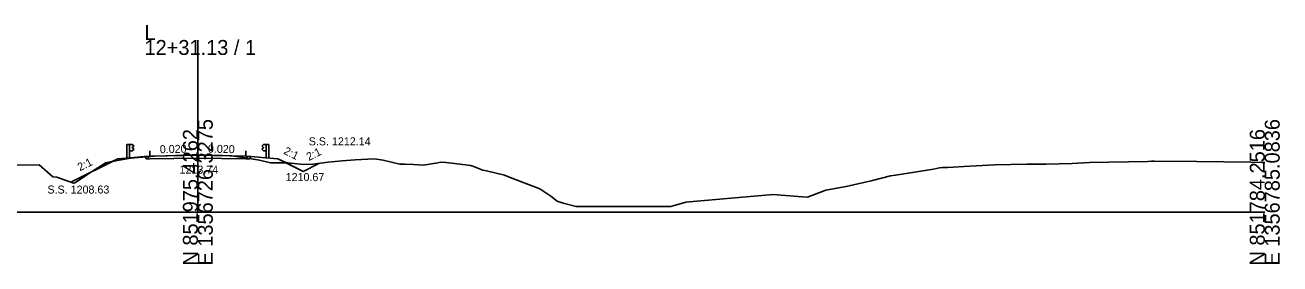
# Model space of a CAD drawing. Extents: x -26 to 3203, y -10 to 4066.
# Drawn here: x 2967.6 to 3202.8, y -9.7 to 35.1 of the extents above; entities that cross this region are included whole.
import ezdxf

# ---------------------------------------------------------------- set-up
doc = ezdxf.new("R2010")
doc.units = 0
for name, color, linetype in [('Exist Cross Section Cell', 7, 'Continuous'), ('Exist XS Center Line Elevation Label', 7, 'Continuous'), ('Exist XS Ground Line', 7, 'Continuous'), ('Prop XS Ditch Standard Text', 7, 'Continuous'), ('Prop XS Dump Level', 7, 'Continuous'), ('Prop XS Earthwork Shape', 7, 'Continuous'), ('Prop XS EOT Tick Mark', 7, 'Continuous'), ('Prop XS Finish Grade', 7, 'Continuous'), ('Prop XS Finish Grade Earthwork', 7, 'Continuous'), ('Prop XS Finish Grade Pavement', 7, 'Continuous'), ('Prop XS Guardrail', 7, 'Continuous'), ('Prop XS Pvmt Edge Slope', 7, 'Continuous'), ('Prop XS SE Text', 7, 'Continuous'), ('Prop XS Side Slope Text', 7, 'Continuous'), ('Prop XS SS Elevation Text', 7, 'Continuous'), ('Prop XS Subgrade Earthwork', 7, 'Continuous')]:
    doc.layers.add(name, color=color, linetype=linetype)

msp = doc.modelspace()

# ---------------------------------------------------------------- linework, layer by layer
at = {"layer": 'Exist Cross Section Cell'}
for p, q in [((3000, 0), (3000, 32.31)), ((2800, 0), (3000, 0)), ((3000, 0), (3200, 0))]:
    msp.add_line(p, q, dxfattribs=at)
at = {"layer": 'Exist XS Ground Line'}
msp.add_lwpolyline([(2965.91, 8.82), (2970.24, 8.91), (2972.79, 6.67), (2973.56, 6.61), (2976.67, 5.44), (2976.92, 5.5), (2977.26, 5.7), (2979.55, 7.26), (2982.41, 9.1), (2982.72, 9.26), (2984.89, 9.68), (2986.66, 10.02), (2987.36, 10.16), (2991.86, 10.54), (2994.24, 10.56), (2998.94, 10.77), (3000, 10.74), (3004.65, 10.63), (3006.35, 10.61), (3008.5, 10.27), (3011.55, 9.76), (3013.62, 9.29), (3016.86, 9.24), (3019.83, 8.98), (3021.58, 8.99), (3024.46, 9.38), (3027.05, 9.67), (3029.5, 9.82), (3033.05, 10), (3034.77, 9.77), (3037.85, 9.05), (3038.78, 9.02), (3040.42, 8.94), (3042.33, 8.84), (3043.83, 9.09), (3044.99, 9.28), (3045.51, 9.37), (3046.47, 9.35), (3048.17, 9.12), (3048.56, 9.08), (3050.16, 8.91), (3051.13, 8.76), (3051.55, 8.67), (3052.5, 8.25), (3053.43, 7.88), (3054.11, 7.78), (3057.51, 6.95), (3058.54, 6.49), (3064.09, 4.4), (3066.18, 3.02), (3067.37, 2.05), (3068.46, 1.71), (3070.89, 1.07), (3075.46, 1.07), (3086.99, 1.07), (3088.17, 1.07), (3088.69, 1.07), (3089.08, 1.18), (3091.48, 1.89), (3092.86, 2.02), (3102.12, 2.8), (3107.13, 3.29), (3107.81, 3.33), (3113.36, 2.92), (3114.29, 2.85), (3117.74, 4.15), (3121.54, 4.84), (3126.24, 5.91), (3129.86, 6.82), (3130.76, 6.93), (3137.9, 8.08), (3139.05, 8.31), (3139.61, 8.38), (3140.55, 8.4), (3144.7, 8.65), (3149.42, 8.91), (3155.37, 9.03), (3159.04, 9.04), (3163.88, 9.17), (3167.17, 9.32), (3178.08, 9.55), (3178.78, 9.57), (3179.29, 9.58), (3187.27, 9.52), (3197.39, 9.37), (3199.47, 9.34), (3200, 9.33)], dxfattribs=at)
at = {"layer": 'Prop XS Dump Level'}
for p, q in [((2991, 10.53), (3000, 10.71)), ((3000, 10.71), (3009, 10.53))]:
    msp.add_line(p, q, dxfattribs=at)
at = {"layer": 'Prop XS Earthwork Shape'}
for points in [[(2982.41, 9.1), (2982.72, 9.26), (2983.84, 9.47), (2980.04, 7.57)], [(2984.89, 9.68), (2986.66, 10.02), (2987.36, 10.16), (2990.04, 10.39), (2989.98, 10.45), (2988, 10.29), (2985, 10.05), (2983.84, 9.47)], [(2990.45, 9.98), (2990.04, 10.39), (2991.86, 10.54), (2994.24, 10.56), (2998.94, 10.77), (3000, 10.74), (3004.65, 10.63), (3006.35, 10.61), (3008.5, 10.27), (3009.65, 10.08), (3009.55, 9.98), (3009, 9.99), (3000, 10.17), (2991, 9.99)], [(3010.02, 10.45), (3012, 10.29), (3015, 10.05), (3016.63, 9.24), (3013.62, 9.29), (3011.55, 9.76), (3009.65, 10.08)], [(2976.16, 5.63), (2980.04, 7.57), (2979.55, 7.26), (2977.26, 5.7), (2976.92, 5.5), (2976.67, 5.44)], [(3019.76, 7.67), (3022.69, 9.14), (3021.58, 8.99), (3019.83, 8.98), (3016.86, 9.24), (3016.63, 9.24)]]:
    msp.add_lwpolyline(points, close=True, dxfattribs=at)
at = {"layer": 'Prop XS EOT Tick Mark'}
for p, q in [((2991, 10.53), (2991, 11.53)), ((3009, 10.53), (3009, 11.53))]:
    msp.add_line(p, q, dxfattribs=at)
at = {"layer": 'Prop XS Finish Grade'}
for p, q in [((2991, 10.53), (2989.98, 10.45)), ((3009, 10.53), (3010.02, 10.45))]:
    msp.add_line(p, q, dxfattribs=at)
at = {"layer": 'Prop XS Finish Grade Earthwork'}
for p, q in [((2976.16, 5.63), (2985, 10.05)), ((2988, 10.29), (2985, 10.05)), ((2989.98, 10.45), (2988, 10.29)), ((3010.02, 10.45), (3012, 10.29)), ((3012, 10.29), (3015, 10.05)), ((3015, 10.05), (3019.76, 7.67)), ((3019.76, 7.67), (3022.69, 9.14))]:
    msp.add_line(p, q, dxfattribs=at)
at = {"layer": 'Prop XS Finish Grade Pavement'}
for p, q in [((2991, 10.53), (3000, 10.71)), ((3000, 10.71), (3009, 10.53))]:
    msp.add_line(p, q, dxfattribs=at)
at = {"layer": 'Prop XS Guardrail'}
for p, q in [((2986.68, 12.69), (2987.18, 12.69)), ((2986.68, 10.19), (2986.68, 12.69)), ((2987.18, 12.69), (2987.68, 12.69)), ((2987.18, 12.69), (2987.18, 10.19)), ((2987.68, 12.69), (2987.97, 12.49)), ((2987.97, 12.37), (2987.68, 12.17)), ((2987.68, 12.17), (2987.68, 12.07)), ((2987.68, 12.07), (2987.97, 11.87)), ((2987.97, 12.49), (2988, 12.43)), ((2988, 12.43), (2987.97, 12.37)), ((2987.97, 11.87), (2988, 11.81)), ((2988, 11.81), (2987.97, 11.75)), ((3012.03, 12.49), (3012, 12.43)), ((3012, 12.43), (3012.03, 12.37)), ((3012.03, 11.87), (3012, 11.81)), ((3012, 11.81), (3012.03, 11.75)), ((3012.32, 12.69), (3012.03, 12.49)), ((3012.03, 12.37), (3012.32, 12.17)), ((3012.32, 12.07), (3012.03, 11.87)), ((3012.82, 12.69), (3012.32, 12.69)), ((3012.32, 12.17), (3012.32, 12.07)), ((3013.32, 12.69), (3012.82, 12.69)), ((3012.82, 12.69), (3012.82, 10.19)), ((3013.32, 10.19), (3013.32, 12.69)), ((2987.68, 11.55), (2987.18, 11.55)), ((2987.97, 11.75), (2987.68, 11.55)), ((3012.03, 11.75), (3012.32, 11.55)), ((3012.32, 11.55), (3012.82, 11.55))]:
    msp.add_line(p, q, dxfattribs=at)
at = {"layer": 'Prop XS Pvmt Edge Slope'}
for p, q in [((2991, 10.53), (2990.45, 9.98)), ((3009, 10.53), (3009.55, 9.98))]:
    msp.add_line(p, q, dxfattribs=at)
at = {"layer": 'Prop XS Subgrade Earthwork'}
for p, q in [((2990.45, 9.98), (2989.98, 10.45)), ((2991, 9.99), (2990.45, 9.98)), ((3000, 10.17), (2991, 9.99)), ((3009, 9.99), (3000, 10.17)), ((3009, 9.99), (3009.55, 9.98)), ((3009.55, 9.98), (3010.02, 10.45))]:
    msp.add_line(p, q, dxfattribs=at)

# ---------------------------------------------------------------- texts
at = {"layer": 'Exist Cross Section Cell'}
for s, p in [('L', (2990, 32.31)), ('12+31.13 / 1', (2990, 29.51))]:
    msp.add_text(s, height=2.8, dxfattribs=at).set_placement(p)
for s, p in [('E 1356726.3275', (3002.8, -10)), ('E 1356785.0836', (3202.8, -10)), ('N 851975.4262', (3000, -10)), ('N 851784.2516', (3200, -10))]:
    msp.add_text(s, height=2.8, rotation=90, dxfattribs=at).set_placement(p)
at = {"layer": 'Exist XS Center Line Elevation Label'}
msp.add_text('1213.74', height=1.5, dxfattribs=at).set_placement((2996.56, 7.24))
at = {"layer": 'Prop XS Ditch Standard Text'}
msp.add_text('1210.67', height=1.5, dxfattribs=at).set_placement((3016.46, 5.85))
at = {"layer": 'Prop XS Dump Level'}
for p in [(2988, 10.25), (3012, 10.25)]:
    msp.add_text('Case1', height=0.04, dxfattribs=at).set_placement(p)
at = {"layer": 'Prop XS SE Text'}
for rotation, p in [(1.1458, (2992.88, 11.07)), (358.8542, (3001.88, 11.18))]:
    msp.add_text('0.020', height=1.5, rotation=rotation, dxfattribs=at).set_placement(p)
at = {"layer": 'Prop XS Side Slope Text'}
for rotation, p in [(333.4349, (3015.95, 11.03)), (26.5651, (3020.8, 9.61)), (26.5651, (2977.9, 7.67))]:
    msp.add_text('2:1', height=1.5, rotation=rotation, dxfattribs=at).set_placement(p)
at = {"layer": 'Prop XS SS Elevation Text'}
for s, p in [('S.S. 1212.14', (3020.79, 12.55)), ('S.S. 1208.63', (2971.81, 3.51))]:
    msp.add_text(s, height=1.5, dxfattribs=at).set_placement(p)

doc.saveas('drawing.dxf')
